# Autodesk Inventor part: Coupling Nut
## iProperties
Author: QBZ
Shininess: 25.0
PropertySet Name: _Private Model Information
Created: 2001-03
Part Number: Coupling Nut
Description: 3/8-16 UNC Coupling Nut
Document SubType Name: Modeling
Designer: QBZ
Material: Steel, Mild
Control State: 0
Master: False
Checked Out: False
PropertySet Name: Design Tracking Control
Density: 7.86
Volumn: 6.490414106817586
Area: 39.92532859875431
PropertySet Name: Model Information
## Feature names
1. Revolution1
2. Extrusion1
3. Chamfer2
